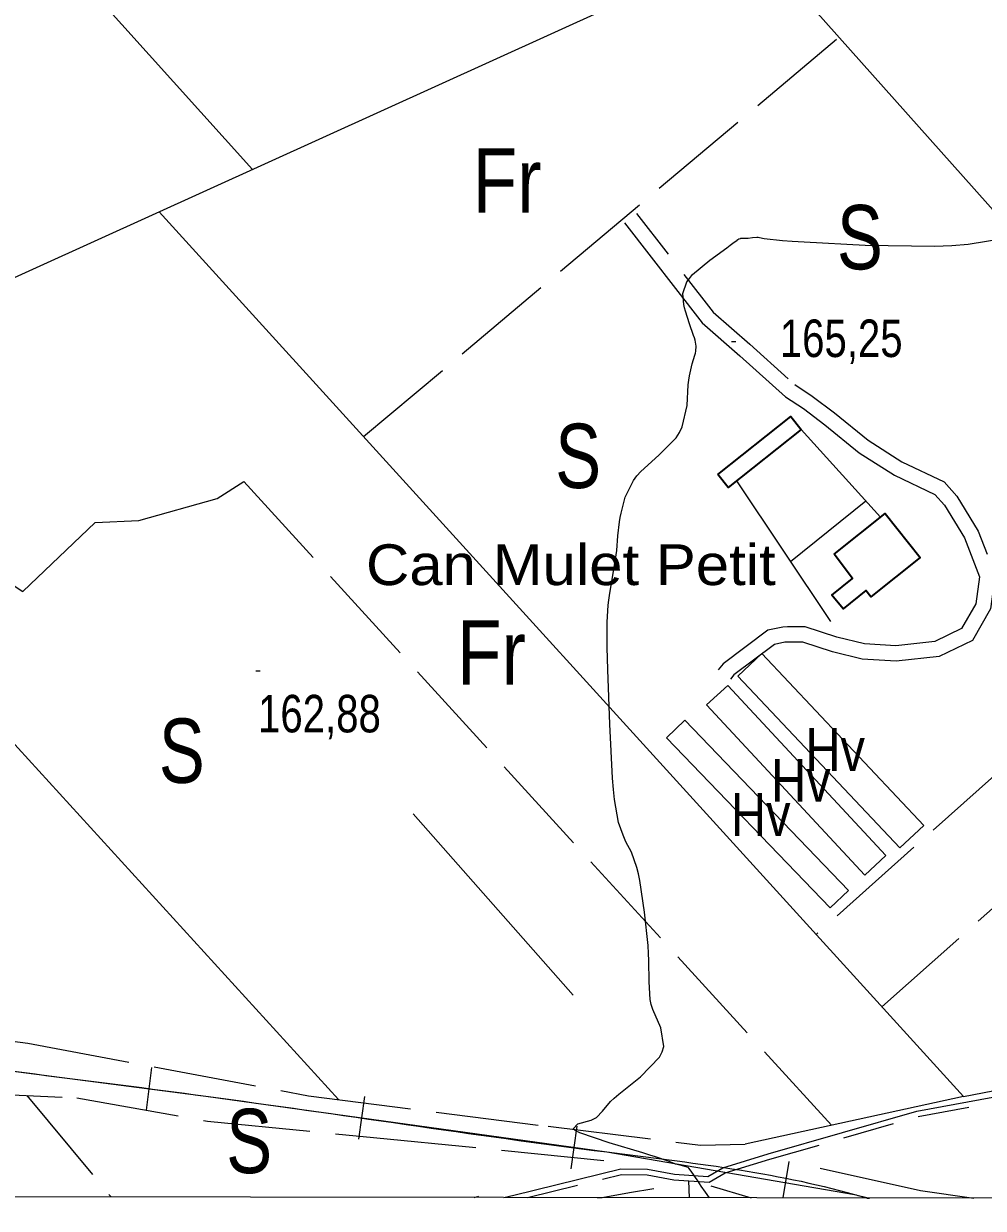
# Model space of a CAD drawing. Extents: x -807245 to 6129983, y -54972206 to 262146364.
# Drawn here: x 490212.4 to 490436.1, y 4381810.3 to 4382086.6 of the extents above; entities that cross this region are included whole.
import ezdxf
from ezdxf.enums import TextEntityAlignment as Align

# ---------------------------------------------------------------- set-up
doc = ezdxf.new("R2010")
doc.units = 0
doc.header["$LTSCALE"] = 4
doc.linetypes.add('LONG_DASHED', pattern=[7.5, 6, -1.5])
doc.linetypes.add('MEDIUM_DASHED', pattern=[4.5, 3, -1.5])
for name, color, linetype, lineweight in [('1', 7, 'Continuous', 13), ('25', 7, 'LONG_DASHED', 25), ('27', 7, 'Continuous', 25), ('30', 7, 'Continuous', 13), ('38', 7, 'Continuous', 25), ('39', 7, 'Continuous', 13), ('47', 7, 'Continuous', 35), ('51', 7, 'Continuous', 13), ('7', 7, 'Continuous', 13), ('9', 7, 'Continuous', 13)]:
    doc.layers.add(name, color=color, linetype=linetype, lineweight=lineweight)
doc.layers.add('31', color=7, linetype='Continuous')
doc.layers.add('5', color=7, linetype='Continuous')

msp = doc.modelspace()

# ---------------------------------------------------------------- linework, layer by layer
at = {"layer": '1'}
msp.add_lwpolyline([(487678, 4384129), (491255.4, 4384123.8), (491252.6, 4381811.5), (487674.1, 4381816.7)], close=True, dxfattribs=at)
at = {"layer": '25'}
for p, q in [((490291.66, 4381990.31), (490402.55, 4382083.48)), ((490464.71, 4381934.48), (490397.17, 4381874.21)), ((490412.49, 4381857.35), (490480.08, 4381917.38)), ((490213.13, 4381836.66), (490232.8, 4381812.98)), ((490367.4, 4381816.76), (490367.53, 4381812.79)), ((490372.65, 4381815.61), (490382.05, 4381812.77))]:
    msp.add_line(p, q, dxfattribs=at)
for points in [[(490194.88, 4382020.42), (490200.54, 4382013.36), (490188.64, 4382005.59), (490172.97, 4382001.8), (490165.88, 4381997.15), (490180.9, 4381975.43), (490189.82, 4381972.47), (490200.63, 4381961.68), (490212.19, 4381954.21), (490229.09, 4381970.26), (490239.28, 4381970.7), (490257.54, 4381975.9), (490263.75, 4381979.79), (490400.77, 4381829.71)], [(489452.44, 4381947.99), (489470.81, 4381945.01), (489504.4, 4381935.18), (489529.88, 4381929.13), (489553.54, 4381927.48), (489566.45, 4381923.64), (489604.56, 4381919.97), (489695.66, 4381907.04), (489772.54, 4381896.5), (489837.07, 4381888.24), (489873.55, 4381883.42), (489910.23, 4381879.72), (489957.75, 4381870.56), (490032.95, 4381858.19), (490087.19, 4381850.38), (490148.03, 4381842.93), (490197.43, 4381837.42), (490224.83, 4381836.07), (490255.25, 4381830.66), (490293.96, 4381826.86), (490348.9, 4381821.39)], [(489902.8, 4381887.88), (489943.4, 4381882.4), (489991.61, 4381875.95), (490041.38, 4381870.45), (490104.43, 4381861.33), (490148.48, 4381856.67), (490213.37, 4381848.87), (490278.82, 4381836.57), (490334.7, 4381829.47), (490370.19, 4381825.08), (490380.61, 4381825.31)], [(490398.1, 4381819.72), (490421.53, 4381814.49), (490433.89, 4381812.69)]]:
    msp.add_lwpolyline(points, dxfattribs=at)
at = {"layer": '27'}
msp.add_spline([(491255.21, 4383970.03), (491244.34, 4383967.52), (491230.36, 4383957.66), (491230.81, 4383957.81), (491230.81, 4383957.81), (491220.15, 4383951.47), (491212.7, 4383943.01), (491205.06, 4383944.23), (491184.85, 4383957.71), (491152.82, 4383981.27), (491128.36, 4384004.58), (491128.29, 4384004.88), (491122.26, 4384021.39), (491095.75, 4384034.59), (491071.07, 4384059.32), (491064.71, 4384065.12)], degree=3, dxfattribs=at)
at = {"layer": '30'}
for points in [[(490378.9, 4381934.46), (490416.66, 4381894.37), (490422.26, 4381899.64), (490384.5, 4381939.73)], [(490371.62, 4381927.71), (490408.48, 4381888.04), (490413.41, 4381892.62), (490376.55, 4381932.29)], [(490362.26, 4381920.08), (490400.41, 4381880.38), (490404.67, 4381884.48), (490366.52, 4381924.18)]]:
    msp.add_lwpolyline(points, close=True, dxfattribs=at)
at = {"layer": '38', "linetype": 'MEDIUM_DASHED'}
for points in [[(490355.32, 4382042.35), (490373.17, 4382019.32), (490381.73, 4382011.84), (490392.18, 4382002.42), (490396.24, 4381999.74), (490401.41, 4381995.85), (490409.32, 4381989.44), (490417.18, 4381984.44), (490427.03, 4381979.71), (490429.95, 4381976.43), (490434.96, 4381968.26), (490437.03, 4381962.89)], [(490438.46, 4381959.18), (490438.9, 4381958.03), (490437.85, 4381950.11), (490433.62, 4381942.77), (490425.84, 4381939.04), (490415.81, 4381937.91), (490407.89, 4381938.39), (490400.97, 4381940.08), (490394.03, 4381942.34), (490390.62, 4381942.39), (490389.88, 4381942.33), (490387.43, 4381941.84), (490378, 4381934.75), (490377.2, 4381933.7)], [(490329.86, 4381812.84), (490351.79, 4381818.26), (490357.74, 4381818.17), (490363.95, 4381816.97), (490372.24, 4381816.44), (490375.94, 4381818.58), (490386.36, 4381821.77), (490420.94, 4381831.74), (490498.48, 4381846.02), (490553.09, 4381855.54)]]:
    msp.add_lwpolyline(points, dxfattribs=at)
at = {"layer": '38'}
for points in [[(490352.5, 4382040.16), (490370.56, 4382016.86), (490379.36, 4382009.17), (490389.99, 4381999.58), (490394.18, 4381996.82), (490399.21, 4381993.03), (490407.23, 4381986.53), (490415.44, 4381981.31), (490424.84, 4381976.8), (490427.07, 4381974.29), (490431.74, 4381966.67), (490435.24, 4381957.6), (490434.4, 4381951.28), (490431.08, 4381945.51), (490424.84, 4381942.52), (490415.72, 4381941.5), (490408.43, 4381941.94), (490401.95, 4381943.52), (490394.62, 4381945.91), (490390.49, 4381945.97), (490389.37, 4381945.87), (490385.93, 4381945.19), (490375.46, 4381937.31), (490374.36, 4381935.87)], [(490324.38, 4381812.85), (490326.65, 4381813.4), (490351.64, 4381819.57), (490357.87, 4381819.48), (490364.12, 4381818.27), (490371.93, 4381817.77), (490375.41, 4381819.79), (490385.99, 4381823.02), (490420.64, 4381833.01), (490498.25, 4381847.31), (490538.08, 4381854.25)]]:
    msp.add_lwpolyline(points, dxfattribs=at)
at = {"layer": '39'}
for p, q in [((490241.03, 4381833.26), (490242.32, 4381843.17)), ((490290.52, 4381826.48), (490291.91, 4381836.39)), ((490340.04, 4381819.58), (490341.43, 4381829.48)), ((490389.44, 4381812.75), (490390.9, 4381821.25))]:
    msp.add_line(p, q, dxfattribs=at)
at = {"layer": '39', "lineweight": 25}
msp.add_line((490409.59, 4381812.73), (490409.61, 4381812.72), dxfattribs=at)
msp.add_lwpolyline([(489563.73, 4381928.23), (489620.66, 4381920.7), (489680.32, 4381912.26), (489735.44, 4381905.59), (489799.91, 4381896.95), (489865.43, 4381887.81), (489926.74, 4381879.18), (489976.6, 4381873.08), (490039.39, 4381865.3), (490107.84, 4381856.38), (490175.25, 4381846.83), (490254.89, 4381836.5), (490348.33, 4381823.47), (490406.14, 4381813.57), (490409.59, 4381812.73)], dxfattribs=at)
at = {"layer": '39'}
msp.add_lwpolyline([(490409.06, 4381812.73), (490409.07, 4381812.73), (490409.08, 4381812.73), (490409.09, 4381812.73), (490409.1, 4381812.73), (490409.11, 4381812.73), (490409.12, 4381812.73), (490409.13, 4381812.73), (490409.15, 4381812.73), (490409.17, 4381812.73), (490409.19, 4381812.73), (490409.21, 4381812.73), (490409.23, 4381812.73), (490409.25, 4381812.73), (490409.27, 4381812.73), (490409.29, 4381812.73), (490409.31, 4381812.73), (490409.33, 4381812.73), (490409.35, 4381812.73), (490409.37, 4381812.73), (490409.39, 4381812.73), (490409.41, 4381812.73), (490409.43, 4381812.73), (490409.45, 4381812.73), (490409.47, 4381812.73), (490409.49, 4381812.73), (490409.51, 4381812.73), (490409.53, 4381812.73), (490409.55, 4381812.73), (490409.57, 4381812.73), (490409.59, 4381812.73), (490409.61, 4381812.72)], dxfattribs=at)
msp.add_spline([(489117.55, 4382698.88), (489119.92, 4382672.68), (489122.01, 4382625.33), (489125.29, 4382585.13), (489126.65, 4382547.13), (489128.77, 4382508.18), (489130.39, 4382475.59), (489130.93, 4382447.55), (489133.21, 4382401.71), (489136.74, 4382363.61), (489144.72, 4382321.33), (489154.17, 4382280.07), (489166.23, 4382246.73), (489180.75, 4382210.53), (489205.22, 4382168.24), (489224.8, 4382133.94), (489257.72, 4382093.12), (489296.35, 4382054.96), (489327.82, 4382028.88), (489364.04, 4382002), (489408.28, 4381978.37), (489453.5, 4381958.06), (489487.73, 4381946.36), (489523.65, 4381936.12), (489563.73, 4381928.23), (489620.66, 4381920.7), (489680.32, 4381912.26), (489735.44, 4381905.59), (489799.91, 4381896.95), (489865.43, 4381887.81), (489926.74, 4381879.18), (489976.6, 4381873.08), (490039.39, 4381865.3), (490107.84, 4381856.38), (490175.25, 4381846.83), (490254.89, 4381836.5), (490348.33, 4381823.47), (490406.14, 4381813.57), (490409.06, 4381812.73)], degree=3, dxfattribs=at)
at = {"layer": '47'}
for points in [[(490374.27, 4381981.46), (490391.29, 4381994.96), (490393.69, 4381991.94), (490376.67, 4381978.44)], [(490401.37, 4381962.86), (490413.24, 4381972.34), (490421.43, 4381962.07), (490409.92, 4381952.91), (490408.74, 4381954.38), (490403.43, 4381950.12), (490400.84, 4381953.34), (490405.66, 4381957.23)]]:
    msp.add_lwpolyline(points, close=True, dxfattribs=at)
at = {"layer": '51'}
for p, q in [((490382.74, 4382105.74), (490567.72, 4381897.73)), ((490140.09, 4381995.55), (490285.83, 4381835.69)), ((490412.19, 4381971.5), (490393.69, 4381991.94)), ((490378.59, 4381979.97), (490400.52, 4381947.16)), ((490391.18, 4381961.14), (490408.76, 4381975.3)), ((490303.25, 4381902.36), (490340.48, 4381860.05)), ((490317.4, 4381812.86), (490318.56, 4381813.15)), ((490346.1, 4381812.82), (490346.11, 4381812.82)), ((490346.11, 4381812.82), (490346.12, 4381812.82)), ((490346.12, 4381812.82), (490346.13, 4381812.82)), ((490346.13, 4381812.82), (490346.14, 4381812.82)), ((490346.14, 4381812.82), (490346.15, 4381812.82)), ((490346.15, 4381812.82), (490346.16, 4381812.82)), ((490346.16, 4381812.82), (490346.17, 4381812.82)), ((490346.17, 4381812.82), (490346.18, 4381812.82)), ((490346.18, 4381812.82), (490346.19, 4381812.82)), ((490346.19, 4381812.82), (490346.2, 4381812.82)), ((490346.2, 4381812.82), (490346.21, 4381812.82)), ((490346.21, 4381812.82), (490346.22, 4381812.82)), ((490346.22, 4381812.82), (490346.23, 4381812.82)), ((490346.23, 4381812.82), (490346.24, 4381812.82)), ((490346.24, 4381812.82), (490346.25, 4381812.82)), ((490346.25, 4381812.82), (490346.26, 4381812.82)), ((490346.26, 4381812.82), (490346.27, 4381812.82)), ((490346.27, 4381812.82), (490346.28, 4381812.82)), ((490346.28, 4381812.82), (490346.29, 4381812.82)), ((490346.29, 4381812.82), (490346.3, 4381812.82)), ((490346.3, 4381812.82), (490346.31, 4381812.82)), ((490346.31, 4381812.82), (490346.32, 4381812.82)), ((490346.32, 4381812.82), (490346.33, 4381812.82)), ((490346.33, 4381812.82), (490346.34, 4381812.82)), ((490346.34, 4381812.82), (490346.35, 4381812.82)), ((490346.35, 4381812.82), (490346.36, 4381812.82)), ((490346.36, 4381812.82), (490346.37, 4381812.82)), ((490346.37, 4381812.82), (490346.38, 4381812.82)), ((490346.38, 4381812.82), (490346.39, 4381812.82)), ((490346.39, 4381812.82), (490346.4, 4381812.82)), ((490346.4, 4381812.82), (490346.41, 4381812.82)), ((490346.41, 4381812.82), (490346.42, 4381812.82)), ((490346.42, 4381812.82), (490346.43, 4381812.82)), ((490346.43, 4381812.82), (490346.44, 4381812.82)), ((490346.44, 4381812.82), (490346.45, 4381812.82)), ((490346.45, 4381812.82), (490346.46, 4381812.82)), ((490346.46, 4381812.82), (490346.47, 4381812.82)), ((490346.47, 4381812.82), (490346.48, 4381812.82)), ((490346.48, 4381812.82), (490346.49, 4381812.82)), ((490346.49, 4381812.82), (490346.5, 4381812.82)), ((490346.5, 4381812.82), (490346.51, 4381812.82)), ((490346.51, 4381812.82), (490346.52, 4381812.82)), ((490346.52, 4381812.82), (490346.53, 4381812.82)), ((490346.53, 4381812.82), (490346.54, 4381812.82)), ((490346.54, 4381812.82), (490346.55, 4381812.82)), ((490346.55, 4381812.82), (490346.56, 4381812.82)), ((490346.56, 4381812.82), (490346.57, 4381812.82)), ((490346.57, 4381812.82), (490346.58, 4381812.82)), ((490346.58, 4381812.82), (490346.59, 4381812.82)), ((490346.59, 4381812.82), (490346.6, 4381812.82)), ((490346.6, 4381812.82), (490346.61, 4381812.82)), ((490346.61, 4381812.82), (490346.62, 4381812.82)), ((490346.62, 4381812.82), (490346.63, 4381812.82)), ((490346.63, 4381812.82), (490346.65, 4381812.82)), ((490346.65, 4381812.82), (490346.67, 4381812.82)), ((490346.67, 4381812.82), (490346.69, 4381812.82)), ((490346.69, 4381812.82), (490346.71, 4381812.82)), ((490346.71, 4381812.82), (490346.73, 4381812.82)), ((490346.73, 4381812.82), (490346.75, 4381812.82)), ((490346.75, 4381812.82), (490346.77, 4381812.82)), ((490346.77, 4381812.82), (490346.79, 4381812.82)), ((490346.79, 4381812.82), (490346.81, 4381812.82)), ((490346.81, 4381812.82), (490346.83, 4381812.82)), ((490346.83, 4381812.82), (490346.85, 4381812.82)), ((490346.85, 4381812.82), (490346.87, 4381812.82)), ((490346.87, 4381812.82), (490346.89, 4381812.82)), ((490346.89, 4381812.82), (490346.91, 4381812.82)), ((490346.91, 4381812.82), (490346.93, 4381812.82)), ((490346.93, 4381812.82), (490346.95, 4381812.82)), ((490346.95, 4381812.82), (490346.97, 4381812.82)), ((490346.97, 4381812.82), (490346.99, 4381812.82)), ((490346.99, 4381812.82), (490347.01, 4381812.82)), ((490347.01, 4381812.82), (490347.03, 4381812.82)), ((490347.03, 4381812.82), (490347.05, 4381812.82)), ((490347.05, 4381812.82), (490347.07, 4381812.82)), ((490347.07, 4381812.82), (490347.09, 4381812.82)), ((490347.09, 4381812.82), (490347.11, 4381812.82)), ((490347.11, 4381812.82), (490347.13, 4381812.82)), ((490347.13, 4381812.82), (490347.15, 4381812.82)), ((490347.15, 4381812.82), (490347.17, 4381812.82)), ((490347.17, 4381812.82), (490347.19, 4381812.82)), ((490347.19, 4381812.82), (490347.21, 4381812.82)), ((490347.21, 4381812.82), (490347.23, 4381812.82)), ((490347.23, 4381812.82), (490347.25, 4381812.82)), ((490347.25, 4381812.82), (490347.27, 4381812.82)), ((490347.27, 4381812.82), (490347.29, 4381812.82)), ((490347.29, 4381812.82), (490347.31, 4381812.82))]:
    msp.add_line(p, q, dxfattribs=at)
for points in [[(489902.11, 4381887.57), (490215.41, 4382029.73), (490575.34, 4382193.24), (490672.95, 4382236.33)], [(490265.79, 4382052.62), (490162.91, 4382166.73), (490119.7, 4382216.96)], [(490244.02, 4382042.73), (490431.52, 4381836.4), (490380.61, 4381825.31)], [(490431.52, 4381836.4), (490527.26, 4381854.92), (490529.8, 4381858.87)], [(490347.31, 4381812.82), (490353.63, 4381814.06), (490359.31, 4381814.94)]]:
    msp.add_lwpolyline(points, dxfattribs=at)
at = {"layer": '7'}
for p, q in [((490377.44, 4382012.44), (490378.44, 4382012.44)), ((490266.55, 4381935.69), (490267.55, 4381935.69))]:
    msp.add_line(p, q, dxfattribs=at)
at = {"layer": '9'}
for points in [[(490368.6, 4382013.91), (490367.64, 4382016.58), (490366.68, 4382019.55), (490366.49, 4382020.32), (490366.33, 4382021.08), (490366.06, 4382023.68), (490366.99, 4382026.37), (490367.6, 4382027.2), (490368.36, 4382028.06), (490372.36, 4382031.44), (490376.38, 4382034.35), (490377.15, 4382034.91), (490377.76, 4382035.37), (490378.74, 4382036.12), (490378.8, 4382036.21), (490378.84, 4382036.24), (490378.89, 4382036.27), (490379.15, 4382036.41), (490379.52, 4382036.53), (490379.64, 4382036.54), (490379.76, 4382036.56), (490380.26, 4382036.55), (490380.89, 4382036.54), (490381.11, 4382036.55), (490381.34, 4382036.58), (490382.3, 4382036.71), (490383.36, 4382036.79), (490383.66, 4382036.78), (490383.96, 4382036.74), (490385.03, 4382036.5), (490389.3, 4382036.04), (490391.61, 4382035.87), (490394.41, 4382035.69), (490408.6, 4382034.9), (490424.75, 4382034.7), (490428.78, 4382034.89), (490432.63, 4382035.19), (490444.96, 4382037.16)], [(490372.29, 4381812.78), (490371.34, 4381814.12), (490370.36, 4381815.53), (490369.55, 4381816.71), (490368.05, 4381819.02), (490367.51, 4381819.7), (490367.3, 4381819.84), (490367.07, 4381819.97), (490366.02, 4381820.28), (490364.77, 4381820.55), (490364.41, 4381820.65), (490364.05, 4381820.77), (490362.7, 4381821.3), (490359.75, 4381822.33), (490358.37, 4381822.76), (490356.76, 4381823.25), (490348.92, 4381825.58), (490342.08, 4381827.92), (490341.08, 4381828.43), (490340.49, 4381828.88), (490341.59, 4381830), (490344.71, 4381830.89), (490345.37, 4381831.21), (490345.96, 4381831.55), (490347.36, 4381833), (490349.23, 4381835.23), (490350.11, 4381836.05), (490351.15, 4381836.97), (490356.22, 4381841.03), (490360.65, 4381845.61), (490361.29, 4381846.85), (490361.68, 4381848.09), (490360.95, 4381852.46), (490359.08, 4381856.71), (490358.74, 4381857.88), (490358.49, 4381859.03), (490358.21, 4381863.14), (490358.19, 4381868.1), (490358.1, 4381869.79), (490357.97, 4381871.62), (490357.17, 4381879.36), (490356.06, 4381886.76), (490355.73, 4381888.37), (490355.39, 4381889.79), (490354.09, 4381893.35), (490352.79, 4381895.83), (490352.46, 4381896.57), (490352.14, 4381897.33), (490351.06, 4381900.28), (490350.14, 4381905.68), (490349.92, 4381907.99), (490349.71, 4381910.65), (490349.05, 4381923.21), (490348.61, 4381935.9), (490348.54, 4381938.65), (490348.48, 4381941.07), (490348.45, 4381947.06), (490348.7, 4381950.99), (490348.82, 4381952.12), (490348.97, 4381953.26), (490349.67, 4381957.52), (490350.39, 4381961.64), (490350.54, 4381962.7), (490350.67, 4381963.73), (490350.96, 4381967.13), (490351.31, 4381970.45), (490351.48, 4381971.42), (490351.68, 4381972.41), (490352.65, 4381976.18), (490354.56, 4381980.07), (490355.36, 4381981.13), (490356.27, 4381982.19), (490360.5, 4381985.96), (490364.54, 4381990.02), (490365.32, 4381991.25), (490365.96, 4381992.54), (490367.06, 4381997.58), (490367.34, 4382002.33), (490367.46, 4382003.43), (490367.6, 4382004.44), (490368.26, 4382007.3), (490368.89, 4382009.3), (490369, 4382009.77), (490369.09, 4382010.19), (490369.21, 4382011.41), (490368.94, 4382012.79), (490368.79, 4382013.32), (490368.6, 4382013.91)]]:
    msp.add_lwpolyline(points, dxfattribs=at)

# ---------------------------------------------------------------- texts
at = {"layer": '31'}
for s, height, width, p in [('Fr', 15, 0.85, (490325.11, 4382042.53)), ('S', 15, 0.8, (490407.36, 4382029.3)), ('S', 15, 0.8, (490341.68, 4381978.3)), ('Fr', 15, 0.85, (490321.46, 4381932.45)), ('S', 15, 0.8, (490249.27, 4381909.55)), ('Hv', 10, 0.85, (490401.59, 4381912.32)), ('Hv', 10, 0.85, (490393.61, 4381905.14)), ('Hv', 10, 0.85, (490384.24, 4381897.16)), ('S', 15, 0.8, (490264.98, 4381818.54))]:
    msp.add_text(s, height=height, dxfattribs=dict(at, width=width)).set_placement(p, align=Align.CENTER)
at = {"layer": '5', "width": 1.1}
msp.add_text('Can Mulet Petit', height=9.5, dxfattribs=at).set_placement((490292.22, 4381955.67))
at = {"layer": '7', "width": 0.8}
for s, p in [('165,25', (490388.69, 4382008.85)), ('162,88', (490267.05, 4381921.32))]:
    msp.add_text(s, height=8.75, dxfattribs=at).set_placement(p)

doc.saveas('drawing.dxf')
